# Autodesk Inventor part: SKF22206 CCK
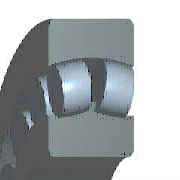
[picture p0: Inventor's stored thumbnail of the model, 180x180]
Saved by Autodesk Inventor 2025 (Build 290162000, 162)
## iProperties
Created: 2024-01
Part Number: SKF22206 CCK
Material: Acciaio, Dolce
Description: Cuscinetti a rulli sferici a fila doppia con foro rastremato SKF
Document SubType Name: Modeling
Standard: SKF
Designer: R5800u
Language: it-IT
Size Designation: SKF22206 CCK
Categories: <MemberInstance><Categories><Category DisplayName="Parti albero" InternalName="7f7aeb1f-a693-4053-b835-cee3144e0d98" Mnemonic="SHFT"><Category DisplayName="Cusc
Density: 7.85 g/cm^3
Appearance: Default
IsCustomPart: 0
Author: R5800u
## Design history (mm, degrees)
workplane "Work Plane1"
pattern_circular "Seriepolare1" dims "d41" = 360 deg
body "Solid1"
revolve "Rivoluzione1" stored, may be unused: angle "d26" = 360 deg
revolve "Rivoluzione2" stored, may be unused: angle "d35" = 90 deg
revolve "Rivoluzione3" stored, may be unused: angle "d38" = 90 deg
revolve "Rivoluzione4" stored, may be unused: angle "d54" = 90 deg
fillet "Raccordo1" dims "d55" = 1 (= r)
sketch "Schizzo3"
  geometry: L1 (-21.62, 0.924)-(-18.329, 1.711); L2 (-20.096, 9.103)-(-23.387, 8.316); L3 (-23.387, 8.316)-(-23.387, 10); L4 (-23.387, 11.684)-(-23.387, 10); L5 (-23.387, 11.684)-(-20.096, 10.897); L6 (-18.329, 18.289)-(-21.62, 19.076); L7 (-21.62, 19.076)-(-21.62, 20); L8 (-21.62, 20)-(-15, 20); L9 (-15, 20)-(-15, 0); L10 (-15, 0)-(-21.62, 0); L11 (-21.62, 0)-(-21.62, 0.924); L12 (-21.62, 19.076)-(-23.387, 11.684); L13 (-21.62, 19.076)-(-25.487, 20); L14 (0, 10)-(-44.739, -0.695); L15 (0, 3.839)-(0, 10); L16 (0, 10)-(-44.739, 20.695); L17 (0, 10)-(-26.52, 10); L18 (0, 3.839)-(0, 10); L19 (-117.926, 0)-(88.303, 0) reference; L20 (0, -66.86)-(0, 97.769) reference; L21 (-31, 20)-(-24.562, 20); L22 (-24.562, 0)-(-31, 0); L23 (-31, 0)-(-31, 20); L24 (-25.487, 20)-(-24.562, 20); A1 r 26.52 centre (-44.739, -0.695) between (-18.329, 1.711) and (-20.096, 9.103); A2 r 26.52 centre (-44.739, 20.695) between (-20.096, 10.897) and (-18.329, 18.289); A3 r 26.52 centre (0, 10) between (-26.52, 10) and (-24.562, 20); A4 r 26.52 centre (0, 10) between (-24.562, 20) and (-24.562, 0)
  constraints: 44 end point, 8 point on circle, 7 collinear, 6 equal length, 5 parallel, 5 vertical, 4 centre point, 2 equal radius, 2 horizontal, 2 point on line, 1 coincident, 1 perpendicular
  dimensions: "d14" = 53.04 diameter of A3 (= msp_dd2); "d16" = 46 distance of A3.centre L14.end (= msp_ds); "d18" = 26.52 radius of A2 (= msp_r1); "d20" = 21.62 horizontal distance of L7.end L15.start (= 0.5 x msp_d2); "d22" = 7.6 distance of L2.start L1.end (= msp_l0); "d24" = 15 horizontal distance of L8.end L15.start (= 0.5 x Diam); "d29" = 20 distance of L8.end L9.end (= B); "d31" = 20 diameter of L10 L17 (= B); "d32" = 62 diameter of L23 L20 (= DD); "d33" = 7.6 diameter of L13 L16 (= msp_l0)
sketch "Schizzo4"
  geometry: L1 (-18.329, 18.289)-(-21.486, 19.044); L2 (-21.486, 19.044)-(-23.253, 11.652); L3 (-23.253, 11.652)-(-20.096, 10.897); L4 (-21.62, 19.076)-(-18.329, 18.289) reference; L5 (-20.096, 10.897)-(-23.387, 11.684) reference; L6 (-18.329, 1.711)-(-21.62, 0.924) reference; L7 (-23.387, 8.316)-(-20.096, 9.103) reference; L8 (-21.486, 19.044)-(-24.643, 19.798); L9 (-23.253, 11.652)-(-26.411, 12.407); A1 r 26.52 centre (-44.739, 20.695) between (-20.096, 10.897) and (-18.329, 18.289) reference; A2 r 26.52 centre (-44.739, -0.695) between (-18.329, 1.711) and (-20.096, 9.103) reference; A3 r 26.52 centre (-44.739, 20.695) between (-20.096, 10.897) and (-18.329, 18.289); A4 r 26.52 centre (0, 10) between (-24.643, 19.798) and (-26.411, 12.407); A5 r 26.52 centre (0, 10) between (24.562, 0) and (-24.562, 0) reference
  constraints: 10 end point, 4 concentric, 4 point on circle, 2 centre point, 2 collinear, 2 parallel, 1 perpendicular
  dimensions: "d34" = 7.04 dimension on A4 L2 (= msp_d0)
sketch "Schizzo6"
  geometry: L1 (-20.096, 19.103)-(-23.253, 18.348); L2 (-23.253, 18.348)-(-21.486, 10.956); L3 (-21.486, 10.956)-(-18.329, 11.711); L4 (-23.387, 18.316)-(-20.096, 19.103) reference; L5 (-18.329, 11.711)-(-21.62, 10.924) reference; L6 (-26.411, 17.593)-(-23.253, 18.348); L7 (-21.486, 10.956)-(-24.643, 10.202); A1 r 26.52 centre (-44.739, 9.305) between (-18.329, 11.711) and (-20.096, 19.103); A2 r 26.52 centre (-44.739, 9.305) between (-18.329, 11.711) and (-20.096, 19.103) reference; A3 r 26.52 centre (0, 20) between (-26.411, 17.593) and (-24.643, 10.202); A4 r 26.52 centre (0, 20) between (24.562, 10) and (-24.562, 10) reference
  constraints: 10 end point, 5 point on circle, 5 symmetric about line, 2 centre point, 2 collinear, 2 concentric, 2 parallel, 1 perpendicular, 3 other
sketch "Schizzo7"
  geometry: L1 (-15, 20)-(15, 20) reference; L2 (-15, 20)-(-15, 0); L3 (-15, 0)-(-15.833, 0); L4 (-15.833, 0)-(-15, 20); L5 (0, -6.2)-(0, 37.2) reference; 1 further point
  constraints: 6 end point, 1 perpendicular, 1 point on line, 1 vertical
  dimensions: "d53" = 0.83333 distance of L2.end L3.end (= 0.0416667 x B)
other parameters: "DD" = 62 [user parameter; used in 4 equation terms], "B" = 20 [user parameter; used in 5 equation terms], "r" = 1 [user parameter; used in 1 equation term], "msp_d0" = 7.04 (= -0.22 x Diam + 0.22 x DD) [user parameter; used in 4 equation terms], "msp_dd2" = 53.04 (= 0.5 x DD + 0.5 x Diam + msp_d0) [user parameter; used in 4 equation terms], "msp_ds" = 46 (= msp_dd2 - msp_d0) [user parameter; used in 2 equation terms], "msp_l0" = 7.6 (= 0.38 x B) [user parameter; used in 2 equation terms], "msp_s" = 10.6 (= 0.53 x B) [user parameter; used in 1 equation term], "msp_d2" = 43.24 (= 0.47 x Diam + 0.47 x DD) [user parameter; used in 1 equation term], "msp_r1" = 26.52 (= 0.5 x msp_dd2) [user parameter; used in 1 equation term], "msp_alfa" = 4.65049 (computed from msp_s, msp_ds) [user parameter], "d0" = 0 (derived), "d4" = 103.2 (derived), "d6" = 31 (derived), "d8" = 0 (derived), "d11" = 15.5 (derived), "d13" = 103.2 (derived), "d17" = 51.6 (derived), "d19" = 42.3 (derived), "d21" = 11.78 (derived), "d25" = 0.06408 (derived), "d36" = 18 deg (= msp_ang), "d37" = 0, "msp_ang" = 18 deg (computed from msp_n) [user parameter; used in 1 equation term], "d47" = 0, "d56" = 0, "d57" = 0, "d58" = 0, "d59" = 0
